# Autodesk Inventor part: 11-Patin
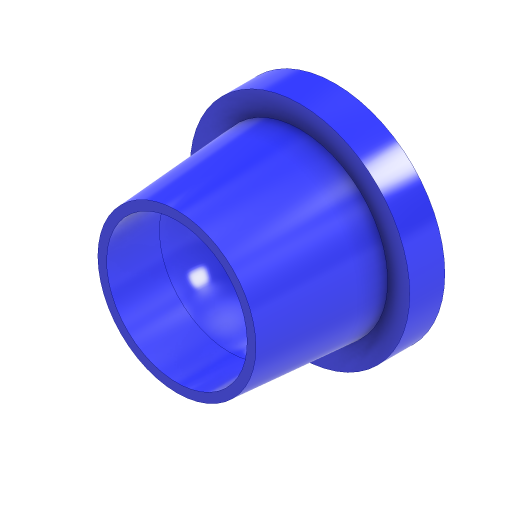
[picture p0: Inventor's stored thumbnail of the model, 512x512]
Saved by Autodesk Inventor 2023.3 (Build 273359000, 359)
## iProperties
Created: 2024-12
Part Number: 11-Patin
Material: Générique
Document SubType Name: Modeling
Designer: Thier
Density: 1 g/cm^3
Appearance: Bleu - Peinture murale - Brillant
Author: Thier
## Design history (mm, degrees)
sketch "Esquisse1"
  geometry: L1 (0, 0)-(6.25, 0); L2 (6.25, 0)-(6.25, 2); L3 (6.25, 2)-(5, 2); L4 (5, 2)-(4.5, 9); L5 (4.5, 9)-(4, 9); L6 (4, 9)-(4, 2); L7 (4, 2)-(0, 2); L8 (0, 2)-(0, 0); 1 further point
  constraints: 16 end point, 4 perpendicular, 2 point on line, 1 horizontal, 1 midpoint, 1 parallel
  dimensions: "d0" = 12.5 diameter of L1.end L8; "d1" = 10 diameter of L3.end L8; "d2" = 9 diameter of L4.end L8; "d3" = 8 vertical distance of L6 point (0, 1); "d4" = 7 distance of L5.end L6.end; "d5" = 2 distance of L2.end L1.end
revolve "Révolution1" sketch "Esquisse1" stored, may be unused: angle "d6" = 90 deg
fillet "Congé1" dims "d7" = 4
node "Solide1"
